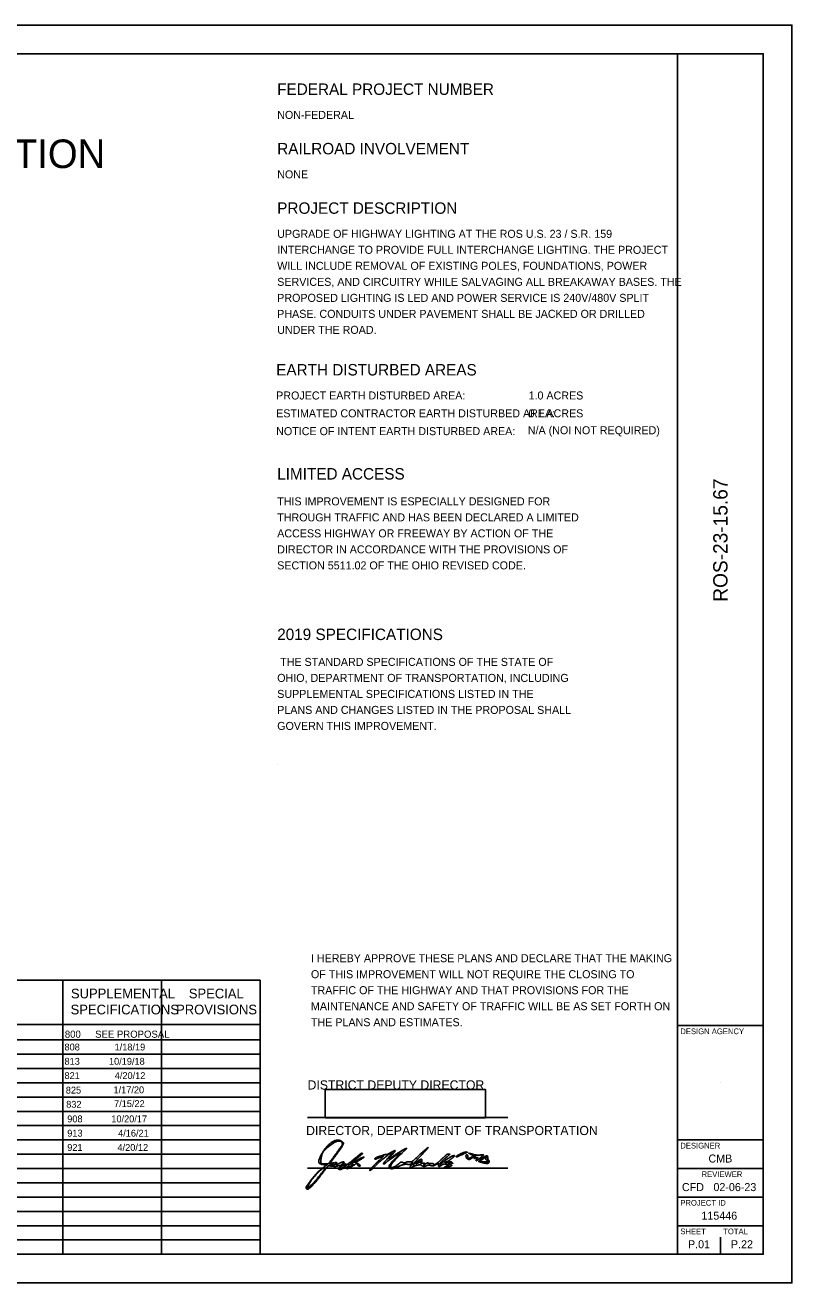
# Model space of a CAD drawing. Extents: x 0 to 34, y 0 to 22.
# Drawn here: x 20.59 to 34, y 0 to 22 of the extents above; entities that cross this region are included whole.
import ezdxf

# ---------------------------------------------------------------- set-up
doc = ezdxf.new("R2010")
doc.units = 0
for name, color, linetype in [('SH_Border', 7, 'Continuous'), ('SH_Cut_Line', 7, 'Continuous'), ('SH_Data', 7, 'Continuous'), ('SH_Text', 7, 'Continuous')]:
    doc.layers.add(name, color=color, linetype=linetype)

msp = doc.modelspace()

# ---------------------------------------------------------------- linework, layer by layer
at = {"layer": 'SH_Border'}
for p, q in [((32, 0.5), (32, 21.5)), ((32, 4.5), (33.5, 4.5)), ((32, 2.5), (33.5, 2.5)), ((32, 2), (33.5, 2)), ((32, 1.5), (33.5, 1.5)), ((32, 1), (33.5, 1))]:
    msp.add_line(p, q, dxfattribs=at)
msp.add_lwpolyline([(1.5, 21.5), (33.5, 21.5), (33.5, 0.5), (1.5, 0.5)], close=True, dxfattribs=at)
at = {"layer": 'SH_Cut_Line'}
msp.add_lwpolyline([(0, 0), (34, 0), (34, 22), (0, 22)], close=True, dxfattribs=at)
at = {"layer": 'SH_Data'}
for p, q in [((25, 9.06), (25, 9.06)), ((11.25, 5.292), (24.7, 5.292)), ((21.25, 0.5), (21.25, 5.292)), ((22.975, 0.5), (22.975, 5.292)), ((24.7, 0.5), (24.7, 5.292)), ((11.25, 4.521), (24.7, 4.521)), ((11.25, 4.25), (24.7, 4.25)), ((11.25, 4), (24.7, 4)), ((11.25, 3.75), (24.7, 3.75)), ((11.25, 3.5), (24.7, 3.5)), ((32.75, 3.5), (32.75, 3.5)), ((11.25, 3.25), (24.7, 3.25)), ((11.25, 3), (24.7, 3)), ((25.531, 2.892), (29.031, 2.892)), ((11.25, 2.75), (24.7, 2.75)), ((11.25, 2.5), (24.7, 2.5)), ((11.25, 2.25), (24.7, 2.25)), ((11.25, 2), (24.7, 2)), ((25.531, 2.006), (29.031, 2.006)), ((11.25, 1.75), (24.7, 1.75)), ((11.25, 1.5), (24.7, 1.5)), ((11.25, 1.25), (24.7, 1.25)), ((11.25, 1), (24.7, 1)), ((11.25, 0.75), (24.7, 0.75)), ((32.375, 0.675), (32.375, 0.675)), ((32.75, 0.5), (32.75, 0.8))]:
    msp.add_line(p, q, dxfattribs=at)
msp.add_lwpolyline([(25.84, 2.884), (25.84, 3.384), (28.64, 3.384), (28.64, 2.884)], close=True, dxfattribs=at)
at = {"layer": 'SH_Text'}
for p, q in [((25.993, 2.211), (25.993, 2.211)), ((28.132, 2.21), (28.132, 2.21)), ((26.314, 2.079), (26.314, 2.079)), ((26.358, 2.121), (26.358, 2.121)), ((26.73, 2.092), (26.73, 2.092)), ((27.507, 2.123), (27.507, 2.123)), ((28.585, 2.104), (28.585, 2.104))]:
    msp.add_line(p, q, dxfattribs=at)
for points in [[(28.396, 2.2), (28.433, 2.222), (28.392, 2.245)], [(25.845, 2.044), (25.876, 2.065), (25.838, 2.066)], [(26.088, 2.024), (26.11, 2.056), (26.068, 2.046)], [(27.456, 2.103), (27.426, 2.077), (27.467, 2.097)], [(28.645, 2.117), (28.701, 2.117), (28.672, 2.139)]]:
    msp.add_lwpolyline(points, dxfattribs=at)
for points in [[(25.782, 2.261), (25.868, 2.412), (26.076, 2.528), (26.142, 2.462)], [(26.133, 2.453), (26.107, 2.495), (25.981, 2.454), (25.885, 2.372)], [(25.993, 2.211), (26.114, 2.374), (26.147, 2.43), (26.133, 2.453)], [(26.142, 2.462), (26.161, 2.443), (26.161, 2.438), (26.142, 2.4)], [(25.838, 2.066), (25.74, 2.067), (25.717, 2.148), (25.782, 2.261)], [(25.885, 2.372), (25.819, 2.315), (25.78, 2.251), (25.769, 2.18)], [(25.847, 2.079), (25.894, 2.079), (25.898, 2.083), (25.993, 2.211)], [(26.027, 2.232), (25.975, 2.163), (25.932, 2.102), (25.932, 2.097)], [(26.142, 2.4), (26.131, 2.377), (26.08, 2.301), (26.027, 2.232)], [(26.372, 2.188), (26.422, 2.231), (26.468, 2.266), (26.473, 2.266)], [(26.473, 2.266), (26.498, 2.267), (26.474, 2.241), (26.389, 2.174)], [(27.005, 2.273), (26.995, 2.283), (26.785, 2.116), (26.707, 2.037)], [(26.708, 2.176), (26.708, 2.186), (26.895, 2.249), (26.911, 2.244)], [(26.73, 2.092), (26.801, 2.16), (26.857, 2.216), (26.853, 2.216)], [(26.853, 2.216), (26.85, 2.216), (26.821, 2.205), (26.789, 2.191)], [(27.145, 2.273), (27.096, 2.245), (26.907, 2.113), (26.894, 2.097)], [(26.911, 2.244), (26.916, 2.242), (26.946, 2.255), (26.977, 2.273)], [(26.927, 2.173), (26.973, 2.224), (27.008, 2.27), (27.005, 2.273)], [(27.008, 2.239), (26.98, 2.207), (26.957, 2.177), (26.957, 2.173)], [(26.957, 2.173), (26.957, 2.169), (26.993, 2.19), (27.035, 2.22)], [(26.977, 2.273), (27.055, 2.32), (27.068, 2.306), (27.008, 2.239)], [(27.171, 2.259), (27.072, 2.165), (26.982, 2.057), (26.982, 2.03)], [(27.035, 2.22), (27.116, 2.276), (27.247, 2.354), (27.263, 2.354)], [(27.08, 2.194), (27.126, 2.243), (27.155, 2.279), (27.145, 2.273)], [(27.263, 2.354), (27.268, 2.354), (27.227, 2.311), (27.171, 2.259)], [(27.315, 2.118), (27.348, 2.115), (27.372, 2.131), (27.49, 2.24)], [(27.521, 2.232), (27.391, 2.095), (27.359, 2.048), (27.441, 2.115)], [(27.49, 2.24), (27.565, 2.309), (27.631, 2.366), (27.637, 2.366)], [(27.637, 2.366), (27.642, 2.366), (27.59, 2.306), (27.521, 2.232)], [(27.97, 2.206), (27.896, 2.145), (27.845, 2.092), (27.845, 2.075)], [(27.879, 2.093), (27.933, 2.142), (28.08, 2.232), (28.097, 2.226)], [(27.898, 2.184), (27.943, 2.228), (27.98, 2.254), (27.998, 2.253)], [(27.998, 2.253), (28.022, 2.253), (28.018, 2.246), (27.97, 2.206)], [(28.097, 2.226), (28.105, 2.223), (28.09, 2.204), (28.063, 2.184)], [(28.132, 2.21), (28.132, 2.222), (28.285, 2.292), (28.304, 2.289)], [(28.204, 2.231), (28.141, 2.202), (28.132, 2.2), (28.132, 2.21)], [(28.304, 2.289), (28.325, 2.285), (28.326, 2.285), (28.204, 2.231)], [(28.333, 2.166), (28.307, 2.18), (28.296, 2.241), (28.32, 2.241)], [(28.32, 2.241), (28.327, 2.241), (28.332, 2.227), (28.332, 2.21)], [(28.332, 2.21), (28.332, 2.173), (28.347, 2.171), (28.396, 2.2)], [(28.392, 2.245), (28.349, 2.269), (28.348, 2.269), (28.451, 2.242)], [(28.456, 2.195), (28.48, 2.225), (28.464, 2.221), (28.408, 2.184)], [(28.451, 2.242), (28.472, 2.237), (28.517, 2.234), (28.551, 2.236)], [(28.551, 2.236), (28.606, 2.239), (28.611, 2.238), (28.591, 2.223)], [(28.591, 2.223), (28.562, 2.201), (28.585, 2.185), (28.619, 2.203)], [(28.653, 2.184), (28.663, 2.21), (28.654, 2.207), (28.592, 2.162)], [(28.619, 2.203), (28.659, 2.225), (28.682, 2.219), (28.682, 2.187)], [(25.838, 2.014), (25.817, 2.035), (25.599, 1.81), (25.553, 1.719)], [(25.594, 1.801), (25.672, 1.902), (25.752, 1.979), (25.845, 2.044)], [(25.623, 1.738), (25.69, 1.807), (25.846, 2.007), (25.838, 2.014)], [(25.769, 2.18), (25.757, 2.106), (25.779, 2.079), (25.847, 2.079)], [(25.927, 2.044), (25.893, 2.047), (25.881, 2.037), (25.805, 1.935)], [(25.939, 2.078), (25.916, 2.077), (25.917, 2.076), (25.943, 2.065)], [(26.068, 2.046), (26.027, 2.036), (26.005, 2.036), (25.927, 2.044)], [(25.932, 2.097), (25.932, 2.092), (25.948, 2.092), (25.967, 2.096)], [(25.982, 2.092), (25.972, 2.085), (25.952, 2.079), (25.939, 2.078)], [(25.943, 2.065), (25.973, 2.053), (26.029, 2.078), (26.011, 2.095)], [(25.967, 2.096), (25.992, 2.102), (25.996, 2.101), (25.982, 2.092)], [(26.011, 2.095), (26.007, 2.1), (26.013, 2.104), (26.025, 2.104)], [(26.025, 2.104), (26.04, 2.104), (26.045, 2.097), (26.04, 2.085)], [(26.04, 2.085), (26.031, 2.062), (26.044, 2.061), (26.076, 2.083)], [(26.087, 1.984), (26.069, 1.991), (26.069, 1.994), (26.088, 2.024)], [(26.076, 2.083), (26.105, 2.103), (26.17, 2.12), (26.17, 2.108)], [(26.154, 2.004), (26.128, 1.988), (26.098, 1.98), (26.087, 1.984)], [(26.155, 2.054), (26.104, 2.026), (26.084, 2.004), (26.111, 2.004)], [(26.111, 2.004), (26.134, 2.004), (26.26, 2.093), (26.372, 2.188)], [(26.148, 2.084), (26.129, 2.071), (26.131, 2.069), (26.164, 2.074)], [(26.17, 2.108), (26.17, 2.104), (26.16, 2.093), (26.148, 2.084)], [(26.205, 2.017), (26.202, 2.026), (26.183, 2.021), (26.154, 2.004)], [(26.164, 2.074), (26.201, 2.08), (26.201, 2.08), (26.155, 2.054)], [(26.319, 2.047), (26.25, 2.003), (26.213, 1.993), (26.205, 2.017)], [(26.26, 2.063), (26.216, 2.022), (26.227, 2.013), (26.285, 2.043)], [(26.314, 2.079), (26.296, 2.085), (26.28, 2.08), (26.26, 2.063)], [(26.389, 2.174), (26.295, 2.101), (26.274, 2.079), (26.318, 2.103)], [(26.285, 2.043), (26.332, 2.066), (26.335, 2.071), (26.314, 2.079)], [(26.318, 2.103), (26.33, 2.109), (26.354, 2.111), (26.371, 2.107)], [(26.404, 2.066), (26.387, 2.09), (26.385, 2.089), (26.319, 2.047)], [(26.362, 2.116), (26.357, 2.116), (26.356, 2.118), (26.358, 2.121)], [(26.358, 2.121), (26.379, 2.139), (26.511, 2.204), (26.516, 2.199)], [(26.516, 2.199), (26.522, 2.193), (26.38, 2.116), (26.362, 2.116)], [(26.371, 2.107), (26.407, 2.098), (26.465, 2.041), (26.439, 2.041)], [(26.439, 2.041), (26.429, 2.041), (26.413, 2.052), (26.404, 2.066)], [(26.62, 1.967), (26.61, 1.967), (26.659, 2.023), (26.73, 2.092)], [(26.707, 2.037), (26.67, 1.998), (26.63, 1.967), (26.62, 1.967)], [(26.789, 2.191), (26.726, 2.164), (26.707, 2.161), (26.708, 2.176)], [(26.861, 2.079), (26.851, 2.079), (26.88, 2.12), (26.927, 2.173)], [(26.894, 2.097), (26.886, 2.087), (26.871, 2.079), (26.861, 2.079)], [(26.973, 2.008), (26.947, 2.033), (26.976, 2.083), (27.08, 2.194)], [(27.172, 2.056), (27.026, 1.998), (26.991, 1.99), (26.973, 2.008)], [(26.982, 2.03), (26.982, 2.022), (26.99, 2.016), (27, 2.016)], [(27, 2.016), (27.022, 2.016), (27.103, 2.061), (27.14, 2.094)], [(27.14, 2.094), (27.16, 2.112), (27.173, 2.114), (27.197, 2.105)], [(27.278, 2.073), (27.249, 2.076), (27.209, 2.07), (27.172, 2.056)], [(27.197, 2.105), (27.217, 2.098), (27.236, 2.098), (27.252, 2.107)], [(27.252, 2.107), (27.265, 2.115), (27.293, 2.12), (27.315, 2.118)], [(27.347, 2.087), (27.332, 2.073), (27.31, 2.069), (27.278, 2.073)], [(27.344, 2.016), (27.326, 2.016), (27.33, 2.049), (27.351, 2.066)], [(27.362, 2.027), (27.359, 2.021), (27.351, 2.016), (27.344, 2.016)], [(27.37, 2.095), (27.37, 2.102), (27.36, 2.098), (27.347, 2.087)], [(27.351, 2.066), (27.361, 2.075), (27.37, 2.088), (27.37, 2.095)], [(27.438, 2.054), (27.4, 2.044), (27.366, 2.032), (27.362, 2.027)], [(27.523, 2.056), (27.512, 2.067), (27.492, 2.066), (27.438, 2.054)], [(27.441, 2.115), (27.49, 2.155), (27.532, 2.166), (27.532, 2.137)], [(27.507, 2.123), (27.507, 2.136), (27.483, 2.127), (27.456, 2.103)], [(27.467, 2.097), (27.489, 2.108), (27.507, 2.12), (27.507, 2.123)], [(27.517, 2.106), (27.506, 2.095), (27.512, 2.091), (27.544, 2.091)], [(27.532, 2.137), (27.532, 2.129), (27.526, 2.114), (27.517, 2.106)], [(27.619, 2.053), (27.588, 2.037), (27.54, 2.038), (27.523, 2.056)], [(27.544, 2.091), (27.581, 2.091), (27.584, 2.089), (27.568, 2.07)], [(27.568, 2.07), (27.556, 2.055), (27.563, 2.057), (27.59, 2.076)], [(27.59, 2.076), (27.611, 2.091), (27.632, 2.1), (27.636, 2.096)], [(27.684, 2.053), (27.657, 2.061), (27.634, 2.061), (27.619, 2.053)], [(27.636, 2.096), (27.64, 2.092), (27.663, 2.089), (27.688, 2.089)], [(27.773, 2.065), (27.735, 2.046), (27.717, 2.044), (27.684, 2.053)], [(27.688, 2.089), (27.712, 2.089), (27.732, 2.084), (27.732, 2.077)], [(27.732, 2.077), (27.732, 2.054), (27.828, 2.116), (27.898, 2.184)], [(27.82, 2.065), (27.82, 2.088), (27.819, 2.088), (27.773, 2.065)], [(27.882, 2.062), (27.837, 2.035), (27.82, 2.036), (27.82, 2.065)], [(27.845, 2.075), (27.845, 2.068), (27.86, 2.076), (27.879, 2.093)], [(27.965, 2.07), (27.926, 2.08), (27.909, 2.078), (27.882, 2.062)], [(28.001, 2.029), (27.954, 2.013), (27.907, 2.019), (27.951, 2.035)], [(27.973, 2.123), (27.923, 2.108), (27.943, 2.094), (27.995, 2.108)], [(27.951, 2.035), (27.965, 2.04), (27.985, 2.047), (27.995, 2.05)], [(27.995, 2.05), (28.006, 2.055), (27.995, 2.062), (27.965, 2.07)], [(28.007, 2.14), (28.004, 2.136), (27.988, 2.128), (27.973, 2.123)], [(27.995, 2.108), (28.033, 2.118), (28.048, 2.118), (28.06, 2.105)], [(28.042, 2.098), (28.005, 2.107), (27.992, 2.084), (28.026, 2.071)], [(28.026, 2.071), (28.057, 2.059), (28.048, 2.044), (28.001, 2.029)], [(28.063, 2.184), (28.036, 2.164), (28.011, 2.144), (28.007, 2.14)], [(28.06, 2.105), (28.073, 2.092), (28.07, 2.091), (28.042, 2.098)], [(28.408, 2.184), (28.368, 2.157), (28.355, 2.154), (28.333, 2.166)], [(28.475, 2.184), (28.442, 2.175), (28.44, 2.177), (28.456, 2.195)], [(28.495, 2.173), (28.51, 2.191), (28.508, 2.192), (28.475, 2.184)], [(28.524, 2.164), (28.492, 2.134), (28.469, 2.141), (28.495, 2.173)], [(28.549, 2.152), (28.58, 2.185), (28.558, 2.196), (28.524, 2.164)], [(28.585, 2.104), (28.53, 2.117), (28.524, 2.124), (28.549, 2.152)], [(28.592, 2.162), (28.549, 2.13), (28.565, 2.117), (28.645, 2.117)], [(28.703, 2.111), (28.695, 2.09), (28.654, 2.087), (28.585, 2.104)], [(28.672, 2.139), (28.652, 2.155), (28.646, 2.168), (28.653, 2.184)], [(28.682, 2.187), (28.682, 2.172), (28.689, 2.152), (28.697, 2.145)], [(28.697, 2.145), (28.704, 2.137), (28.707, 2.122), (28.703, 2.111)], [(25.805, 1.935), (25.652, 1.733), (25.507, 1.604), (25.507, 1.671)], [(25.507, 1.671), (25.507, 1.681), (25.547, 1.739), (25.594, 1.801)], [(25.553, 1.719), (25.521, 1.658), (25.553, 1.667), (25.623, 1.738)]]:
    msp.add_open_spline(points, degree=2, dxfattribs=at)

# ---------------------------------------------------------------- texts
at = {"layer": 'SH_Data'}
for s, height, p in [('FEDERAL PROJECT NUMBER', 0.2, (25, 20.78)), ('NON-FEDERAL', 0.14, (25, 20.36)), ('DEPARTMENT OF TRANSPORTATION', 0.5, (9.92, 19.5)), ('RAILROAD INVOLVEMENT', 0.2, (25, 19.74)), ('NONE', 0.14, (25, 19.32)), ('PROJECT DESCRIPTION', 0.2, (25, 18.7)), ('UPGRADE OF HIGHWAY LIGHTING AT THE ROS U.S. 23 / S.R. 159 ', 0.14, (25, 18.28)), ('INTERCHANGE TO PROVIDE FULL INTERCHANGE LIGHTING. THE PROJECT ', 0.14, (25, 18)), ('WILL INCLUDE REMOVAL OF EXISTING POLES, FOUNDATIONS, POWER ', 0.14, (25, 17.72)), ('SERVICES, AND CIRCUITRY WHILE SALVAGING ALL BREAKAWAY BASES. THE ', 0.14, (25, 17.44)), ('PROPOSED LIGHTING IS LED AND POWER SERVICE IS 240V/480V SPLIT ', 0.14, (25, 17.16)), ('PHASE. CONDUITS UNDER PAVEMENT SHALL BE JACKED OR DRILLED ', 0.14, (25, 16.88)), ('UNDER THE ROAD. ', 0.14, (25, 16.6)), ('EARTH DISTURBED AREAS', 0.2, (24.982, 15.872)), ('PROJECT EARTH DISTURBED AREA:', 0.14, (24.982, 15.452)), ('1.0 ACRES', 0.14, (29.396, 15.452)), ('ESTIMATED CONTRACTOR EARTH DISTURBED AREA:', 0.14, (24.982, 15.14)), ('0.1 ACRES', 0.14, (29.396, 15.14)), ('NOTICE OF INTENT EARTH DISTURBED AREA:', 0.14, (24.982, 14.828)), ('N/A (NOI NOT REQUIRED)', 0.14, (29.383, 14.844)), ('LIMITED ACCESS', 0.2, (25, 14.052)), ('THIS IMPROVEMENT IS ESPECIALLY DESIGNED FOR', 0.14, (25, 13.6)), ('THROUGH TRAFFIC AND HAS BEEN DECLARED A LIMITED', 0.14, (25, 13.32)), ('ACCESS HIGHWAY OR FREEWAY BY ACTION OF THE', 0.14, (25, 13.04)), ('DIRECTOR IN ACCORDANCE WITH THE PROVISIONS OF', 0.14, (25, 12.76)), ('SECTION 5511.02 OF THE OHIO REVISED CODE.', 0.14, (25, 12.48)), ('2019 SPECIFICATIONS', 0.2, (25, 11.244)), (' THE STANDARD SPECIFICATIONS OF THE STATE OF', 0.14, (25, 10.792)), ('OHIO, DEPARTMENT OF TRANSPORTATION, INCLUDING', 0.14, (25, 10.512)), ('SUPPLEMENTAL SPECIFICATIONS LISTED IN THE', 0.14, (25, 10.232)), ('PLANS AND CHANGES LISTED IN THE PROPOSAL SHALL', 0.14, (25, 9.952)), ('GOVERN THIS IMPROVEMENT.', 0.14, (25, 9.672)), ('I HEREBY APPROVE THESE PLANS AND DECLARE THAT THE MAKING ', 0.14, (25.59, 5.609)), ('OF THIS IMPROVEMENT WILL NOT REQUIRE THE CLOSING TO ', 0.14, (25.59, 5.329)), ('SUPPLEMENTAL', 0.17, (21.393, 4.976)), ('SPECIAL', 0.17, (23.454, 4.976)), ('TRAFFIC OF THE HIGHWAY AND THAT PROVISIONS FOR THE ', 0.14, (25.59, 5.049)), ('SPECIFICATIONS', 0.17, (21.387, 4.696)), ('PROVISIONS', 0.17, (23.232, 4.696)), ('MAINTENANCE AND SAFETY OF TRAFFIC WILL BE AS SET FORTH ON ', 0.14, (25.59, 4.769)), ('THE PLANS AND ESTIMATES.', 0.14, (25.59, 4.489)), ('DESIGN AGENCY', 0.1, (32.05, 4.35)), ('DESIGNER', 0.1, (32.05, 2.35)), ('CMB', 0.14, (32.542, 2.105)), ('REVIEWER', 0.1, (32.422, 1.85)), ('CFD', 0.14, (32.078, 1.605)), ('02-06-23', 0.14, (32.629, 1.605)), ('PROJECT ID', 0.1, (32.05, 1.35)), ('115446', 0.14, (32.419, 1.105)), ('SHEET', 0.1, (32.05, 0.85)), ('TOTAL', 0.1, (32.8, 0.85)), ('P.01', 0.14, (32.184, 0.605)), ('P.22', 0.14, (32.935, 0.605))]:
    msp.add_text(s, height=height, dxfattribs=at).set_placement(p)
msp.add_text('ROS-23-15.67', height=0.25, rotation=90, dxfattribs=at).set_placement((32.875, 11.914))
at = {"layer": 'SH_Text'}
for s, height, p in [('800', 0.125, (21.286, 4.287)), ('SEE PROPOSAL', 0.125, (21.816, 4.287)), ('808', 0.12, (21.28, 4.065)), ('1/18/19', 0.12, (22.156, 4.065)), ('813', 0.12, (21.28, 3.815)), ('10/19/18', 0.12, (22.058, 3.815)), ('821', 0.12, (21.28, 3.565)), ('4/20/12', 0.12, (22.159, 3.565)), ('DISTRICT DEPUTY DIRECTOR', 0.16, (25.531, 3.382)), ('825', 0.12, (21.303, 3.311)), ('1/17/20', 0.12, (22.137, 3.316)), ('832', 0.12, (21.31, 3.063)), ('7/15/22', 0.12, (22.147, 3.075)), ('908', 0.12, (21.328, 2.808)), ('10/20/17', 0.12, (22.099, 2.808)), ('913', 0.12, (21.328, 2.558)), ('4/16/21', 0.12, (22.218, 2.558)), ('DIRECTOR, DEPARTMENT OF TRANSPORTATION', 0.16, (25.506, 2.585)), ('921', 0.12, (21.328, 2.308)), ('4/20/12', 0.12, (22.207, 2.308))]:
    msp.add_text(s, height=height, dxfattribs=at).set_placement(p)

doc.saveas('drawing.dxf')
